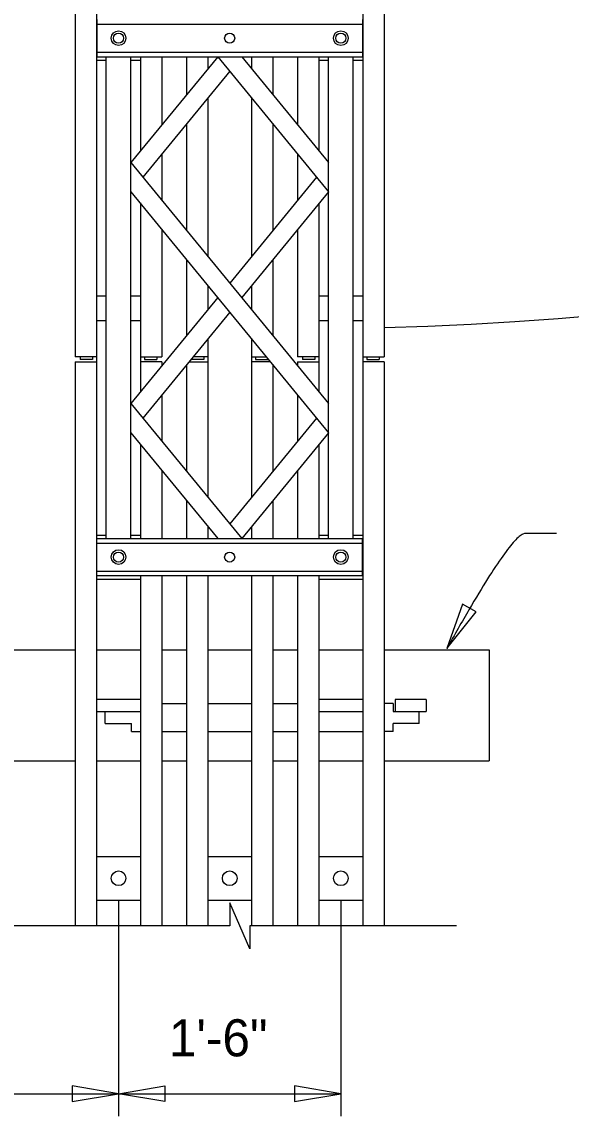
# Model space of a CAD drawing. Extents: x -58 to 62, y 0 to 81.
# Drawn here: x 42.87 to 46.57, y 2.49 to 9.87 of the extents above; entities that cross this region are included whole.
import ezdxf

# ---------------------------------------------------------------- set-up
doc = ezdxf.new("R2010")
doc.units = 0
for name, color, linetype in [('Dimension', 7, 'Continuous'), ('GroundLines', 7, 'Continuous'), ('SteelMisc', 7, 'Continuous'), ('SteelMisc_h', 7, 'Continuous'), ('Symbols', 7, 'Continuous')]:
    doc.layers.add(name, color=color, linetype=linetype)

msp = doc.modelspace()

# ---------------------------------------------------------------- linework, layer by layer
at = {"layer": 'Dimension'}
for p, q in [((43.5198, 3.9415), (43.5198, 2.4889)), ((45.0198, 3.9415), (45.0198, 2.4889)), ((16.5199, 2.6401), (45.0198, 2.6401))]:
    msp.add_line(p, q, dxfattribs=at)
for points in [[(45.7357, 5.6437), (45.9339, 5.8909), (45.8414, 5.9424)], [(43.5198, 2.6401), (43.2074, 2.693), (43.2074, 2.5872)], [(43.5198, 2.6401), (43.8322, 2.693), (43.8322, 2.5872)], [(45.0198, 2.6401), (44.7074, 2.693), (44.7074, 2.5872)]]:
    msp.add_lwpolyline(points, close=True, dxfattribs=at)
msp.add_open_spline([(46.4753, 6.4185), (46.3608, 6.4185), (46.1671, 6.4185), (45.7357, 5.6437)], degree=2, dxfattribs=at)
at = {"layer": 'GroundLines'}
msp.add_arc((44.7698, 29.8013), 22, 271.41066, 319.81021, dxfattribs=at)
at = {"layer": 'SteelMisc'}
for p, q in [((43.3716, 27.8428), (43.3716, 7.6107)), ((45.168, 27.8428), (45.168, 7.6107)), ((43.3716, 17.8428), (43.3716, 3.773)), ((45.168, 17.8428), (45.168, 3.773)), ((43.2281, 17.576), (43.2281, 7.6107)), ((45.3114, 17.576), (45.3114, 7.6107)), ((43.3739, 9.8843), (43.3739, 9.6343)), ((43.3739, 9.8538), (45.1656, 9.8538)), ((45.1656, 9.8843), (45.1656, 9.6343)), ((43.3716, 9.6111), (43.4364, 9.6111)), ((43.3739, 9.6648), (45.1656, 9.6648)), ((43.3739, 9.6343), (45.1656, 9.6343)), ((43.4364, 6.3843), (43.4364, 9.6343)), ((43.6031, 6.3843), (43.6031, 9.6343)), ((44.1889, 9.6343), (43.6031, 8.9204)), ((43.6031, 9.6111), (43.668, 9.6111)), ((43.668, 9.6343), (43.668, 8.9994)), ((43.668, 9.6343), (43.668, 8.9979)), ((43.8114, 9.6343), (43.8114, 9.1742)), ((43.8114, 9.6343), (43.8114, 9.1746)), ((43.9781, 9.6343), (43.9781, 9.3774)), ((44.1216, 9.6343), (44.1216, 9.5522)), ((44.1889, 9.6343), (44.9363, 8.7233)), ((44.3506, 9.6343), (44.9363, 8.9204)), ((44.418, 9.6343), (44.418, 9.5521)), ((44.5614, 9.6343), (44.5614, 9.3773)), ((44.7281, 9.6343), (44.7281, 9.1741)), ((44.7281, 9.6343), (44.7281, 9.1736)), ((44.8716, 9.6343), (44.8716, 8.9993)), ((44.8716, 9.6343), (44.8716, 8.9976)), ((44.8716, 9.6111), (44.9363, 9.6111)), ((44.9363, 6.3843), (44.9363, 9.6343)), ((45.103, 6.3843), (45.103, 9.6343)), ((45.103, 9.6111), (45.168, 9.6111)), ((44.2697, 9.5358), (43.684, 8.8218)), ((44.1216, 9.3552), (44.1216, 8.2885)), ((44.418, 9.355), (44.418, 8.2886)), ((43.9781, 9.1804), (43.9781, 8.4633)), ((44.5614, 9.1802), (44.5614, 8.4634)), ((43.8114, 8.9772), (43.8114, 8.6665)), ((43.8114, 8.9699), (43.8114, 8.6614)), ((44.7281, 8.9771), (44.7281, 8.6666)), ((44.7281, 8.9739), (44.7281, 8.6671)), ((43.6031, 8.9204), (44.9363, 7.2954)), ((44.8555, 8.8218), (44.2697, 8.1079)), ((43.6031, 8.7233), (44.9363, 7.0983)), ((44.9363, 8.7233), (44.3506, 8.0093)), ((43.668, 8.6484), (43.668, 7.6107)), ((43.668, 8.6442), (43.668, 7.3744)), ((44.8716, 8.6443), (44.8716, 7.3743)), ((44.8716, 8.6427), (44.8716, 7.6107)), ((43.8114, 8.4694), (43.8114, 7.6107)), ((43.8114, 8.4677), (43.8114, 7.6107)), ((44.7281, 8.47), (44.7281, 7.6107)), ((44.7281, 8.4695), (44.7281, 7.6107)), ((43.9781, 8.2662), (43.9781, 7.7524)), ((44.5614, 8.2663), (44.5614, 7.7523)), ((44.1216, 8.0914), (44.1216, 7.9272)), ((44.418, 8.0915), (44.418, 7.9271)), ((43.4364, 8.0199), (43.3716, 8.0199)), ((43.668, 8.0199), (43.6031, 8.0199)), ((44.1889, 8.0093), (43.6031, 7.2954)), ((44.9363, 8.0199), (44.8716, 8.0199)), ((45.168, 8.0199), (45.103, 8.0199)), ((44.2697, 7.9108), (43.684, 7.1968)), ((43.4364, 7.8533), (43.3716, 7.8533)), ((43.668, 7.8533), (43.6031, 7.8533)), ((44.9363, 7.8533), (44.8716, 7.8533)), ((45.168, 7.8533), (45.103, 7.8533)), ((44.1216, 7.7302), (44.1216, 6.6635)), ((44.418, 7.73), (44.418, 6.6636)), ((43.3715, 7.6107), (43.228, 7.6107)), ((43.3715, 7.6107), (43.228, 7.6107)), ((43.2614, 7.6107), (43.2614, 7.5928)), ((43.3447, 7.6107), (43.3447, 7.5928)), ((43.6679, 7.6107), (43.8113, 7.6107)), ((43.6679, 7.6107), (43.8113, 7.6107)), ((43.6947, 7.6107), (43.6947, 7.5928)), ((43.778, 7.6107), (43.778, 7.5928)), ((44.1215, 7.6107), (44.0235, 7.6107)), ((44.0947, 7.6107), (44.0947, 7.5928)), ((44.4179, 7.6107), (44.5159, 7.6107)), ((44.4447, 7.6107), (44.4447, 7.5928)), ((44.8716, 7.6107), (44.7281, 7.6107)), ((44.8716, 7.6107), (44.7281, 7.6107)), ((44.7615, 7.6107), (44.7615, 7.5928)), ((44.8448, 7.6107), (44.8448, 7.5928)), ((45.168, 7.6107), (45.3114, 7.6107)), ((45.168, 7.6107), (45.3114, 7.6107)), ((45.1948, 7.6107), (45.1948, 7.5928)), ((45.2781, 7.6107), (45.2781, 7.5928)), ((43.228, 7.576), (43.3715, 7.576)), ((43.2281, 7.576), (43.2281, 3.773)), ((43.3447, 7.5928), (43.2614, 7.5928)), ((43.8113, 7.576), (43.6679, 7.576)), ((43.6947, 7.5928), (43.778, 7.5928)), ((43.8114, 7.576), (43.8114, 7.5492)), ((43.9781, 7.5554), (43.9781, 6.8383)), ((43.9951, 7.576), (44.1215, 7.576)), ((44.0114, 7.5959), (44.0114, 7.5928)), ((44.0947, 7.5928), (44.0114, 7.5928)), ((44.5444, 7.576), (44.4179, 7.576)), ((44.4447, 7.5928), (44.528, 7.5928)), ((44.528, 7.596), (44.528, 7.5928)), ((44.5614, 7.5552), (44.5614, 6.8384)), ((44.7281, 7.576), (44.7281, 7.5491)), ((44.7281, 7.576), (44.8716, 7.576)), ((44.8448, 7.5928), (44.7615, 7.5928)), ((45.3114, 7.576), (45.168, 7.576)), ((45.1948, 7.5928), (45.2781, 7.5928)), ((45.3114, 7.576), (45.3114, 3.773)), ((43.8114, 7.3522), (43.8114, 7.0415)), ((44.7281, 7.3521), (44.7281, 7.0416)), ((43.6031, 7.2954), (44.3506, 6.3843)), ((44.8555, 7.1968), (44.2697, 6.4829)), ((43.6031, 7.0983), (44.1889, 6.3843)), ((44.9363, 7.0983), (44.3506, 6.3843)), ((43.668, 7.0192), (43.668, 6.3843)), ((44.8716, 7.0193), (44.8716, 6.3843)), ((43.8114, 6.8444), (43.8114, 6.3843)), ((44.7281, 6.8445), (44.7281, 6.3843)), ((43.9781, 6.6412), (43.9781, 6.3843)), ((44.5614, 6.6413), (44.5614, 6.3843)), ((44.1216, 6.4664), (44.1216, 6.3843)), ((44.418, 6.4665), (44.418, 6.3843)), ((43.3716, 6.4077), (43.4364, 6.4077)), ((43.3739, 6.3843), (45.1656, 6.3843)), ((43.3739, 6.1343), (43.3739, 6.3843)), ((43.3739, 6.3538), (45.1656, 6.3538)), ((43.6031, 6.4077), (43.668, 6.4077)), ((44.8716, 6.4077), (44.9363, 6.4077)), ((45.103, 6.4077), (45.168, 6.4077)), ((45.1656, 6.1343), (45.1656, 6.3843)), ((43.3739, 6.1648), (45.1656, 6.1648)), ((43.3739, 6.1343), (45.1656, 6.1343)), ((43.668, 6.1343), (43.668, 3.773)), ((43.8114, 6.1343), (43.8114, 3.773)), ((43.9781, 6.1343), (43.9781, 3.773)), ((44.1216, 6.1343), (44.1216, 3.773)), ((44.418, 6.1343), (44.418, 3.773)), ((44.5614, 6.1343), (44.5614, 3.773)), ((44.7281, 6.1343), (44.7281, 3.773)), ((44.8716, 6.1343), (44.8716, 3.773)), ((43.3716, 6.1112), (43.668, 6.1112)), ((44.8716, 6.1112), (45.168, 6.1112)), ((43.3716, 5.6345), (43.668, 5.6345)), ((43.8114, 5.6345), (43.9781, 5.6345)), ((44.1216, 5.6345), (44.418, 5.6345)), ((44.5614, 5.6345), (44.7281, 5.6345)), ((44.8716, 5.6345), (45.168, 5.6345)), ((45.3114, 5.6345), (46.0198, 5.6345)), ((46.0198, 5.6345), (46.0198, 4.8846)), ((43.668, 5.2999), (43.3716, 5.2999)), ((43.8114, 5.2711), (43.9781, 5.2711)), ((44.1216, 5.2711), (44.418, 5.2711)), ((44.5614, 5.2711), (44.7281, 5.2711)), ((45.168, 5.2999), (44.8716, 5.2999)), ((45.168, 5.2999), (44.8716, 5.2999)), ((45.3729, 5.2714), (45.3114, 5.2714)), ((45.3729, 5.2714), (45.3729, 5.219)), ((45.595, 5.2999), (45.3867, 5.2999)), ((45.3867, 5.2999), (45.3867, 5.219)), ((45.595, 5.2999), (45.595, 5.219)), ((43.3716, 5.219), (43.668, 5.219)), ((43.4304, 5.1359), (43.4304, 5.219)), ((44.8716, 5.219), (45.168, 5.219)), ((44.8716, 5.219), (45.168, 5.219)), ((45.3729, 5.219), (45.595, 5.219)), ((45.549, 5.1359), (45.549, 5.219)), ((43.4304, 5.1359), (43.6065, 5.1359)), ((43.6065, 5.0835), (43.6065, 5.1359)), ((45.549, 5.1359), (45.3729, 5.1359)), ((45.3729, 5.0835), (45.3729, 5.1359)), ((43.6065, 5.0835), (43.668, 5.0835)), ((43.8114, 5.0835), (43.9781, 5.0835)), ((44.1216, 5.0835), (44.418, 5.0835)), ((44.5614, 5.0835), (44.7281, 5.0835)), ((44.8716, 5.0835), (45.168, 5.0835)), ((45.3729, 5.0835), (45.3114, 5.0835)), ((43.3716, 4.8846), (43.668, 4.8846)), ((43.8114, 4.8846), (43.9781, 4.8846)), ((44.1216, 4.8846), (44.418, 4.8846)), ((44.5614, 4.8846), (44.7281, 4.8846)), ((44.8716, 4.8846), (45.168, 4.8846)), ((45.3114, 4.8846), (46.0198, 4.8846)), ((43.3716, 4.241), (43.668, 4.241)), ((44.1216, 4.241), (44.418, 4.241)), ((44.8716, 4.241), (45.168, 4.241)), ((43.3716, 3.9445), (43.668, 3.9445)), ((44.1216, 3.9445), (44.418, 3.9445)), ((44.8716, 3.9445), (45.168, 3.9445))]:
    msp.add_line(p, q, dxfattribs=at)
for centre, radius in [((43.5198, 9.7593), 0.0495), ((43.5198, 9.7593), 0.0339), ((44.2697, 9.7593), 0.0339), ((45.0198, 9.7593), 0.0495), ((45.0197, 9.7593), 0.0339), ((43.5198, 6.2594), 0.0495), ((43.5198, 6.2593), 0.0339), ((44.2697, 6.2593), 0.0339), ((45.0198, 6.2594), 0.0495), ((45.0197, 6.2593), 0.0339), ((43.5198, 4.0927), 0.0495), ((44.2698, 4.0927), 0.0495), ((45.0198, 4.0927), 0.0495)]:
    msp.add_circle(centre, radius, dxfattribs=at)
at = {"layer": 'SteelMisc_h'}
for p, q in [((18.3115, 5.6345), (43.2281, 5.6345)), ((18.3115, 4.8846), (43.2281, 4.8846))]:
    msp.add_line(p, q, dxfattribs=at)
at = {"layer": 'Symbols'}
msp.add_lwpolyline([(45.7995, 3.773), (44.4051, 3.773), (44.4051, 3.618), (44.2701, 3.928), (44.2701, 3.773), (40.4497, 3.773)], dxfattribs=at)

# ---------------------------------------------------------------- texts
at = {"layer": 'Dimension'}
msp.add_text('1\'-6"', height=0.25, dxfattribs=at).set_placement((43.8597, 2.892))

doc.saveas('drawing.dxf')
